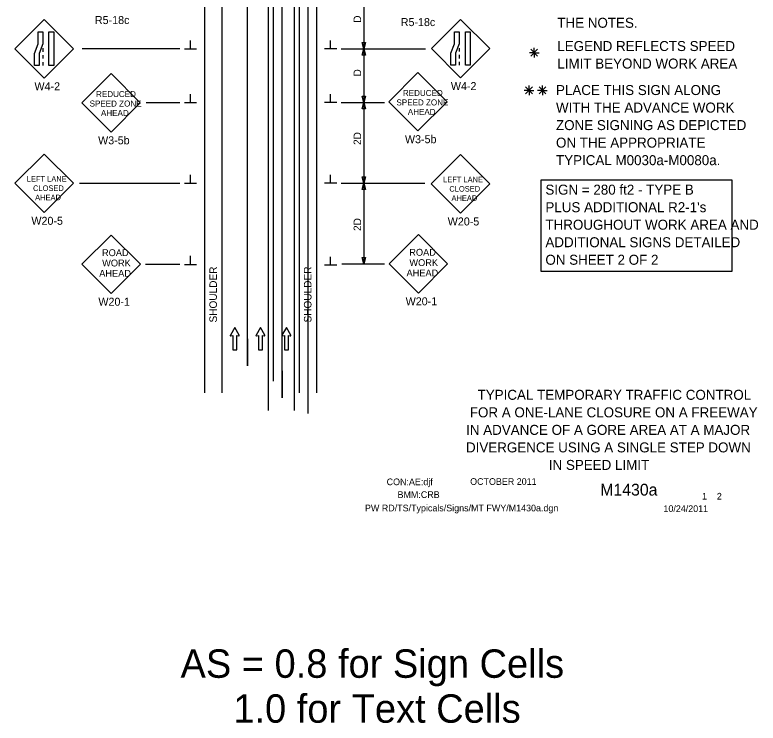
# Model space of a CAD drawing. Extents: x 16729 to 18500, y 5737 to 6974.
# Drawn here: x 16745 to 17436, y 5737 to 6395 of the extents above; entities that cross this region are included whole.
import ezdxf

# ---------------------------------------------------------------- set-up
doc = ezdxf.new("R2010")
doc.units = 0
for name, color, linetype in [('ALI_LEGAL_EX', 7, 'Continuous'), ('BORDER', 7, 'Continuous'), ('BORDER_SIGNAL_WO', 7, 'Continuous'), ('MT_SCRATCH_LEVEL_E', 7, 'Continuous'), ('PAVT_EDGE_EX', 7, 'Continuous'), ('TRAFFIC_SIGNS_PR', 7, 'Continuous'), ('TYPICAL_TEXT_DIMEN_EX', 7, 'Continuous'), ('TYPICAL_TEXT_DIMEN_PR', 7, 'Continuous')]:
    doc.layers.add(name, color=color, linetype=linetype)

msp = doc.modelspace()

# ---------------------------------------------------------------- linework, layer by layer
at = {"layer": 'ALI_LEGAL_EX'}
for p, q in [((16980.68, 6974.12), (16980.68, 6155.98)), ((17004.68, 6974.12), (17004.68, 6155.98)), ((16980.68, 6891.53), (16980.68, 6027.61)), ((17004.68, 6891.53), (17004.68, 6027.61)), ((16961.51, 6069.17), (16961.51, 6569.52)), ((16985.51, 6054.68), (16985.51, 6555.03)), ((16993.65, 6039.29), (16993.65, 6539.64)), ((17017.65, 6024.8), (17017.65, 6525.15))]:
    msp.add_line(p, q, dxfattribs=at)
for points in [[(16961.51, 6369.17), (16961.51, 6394.17)], [(16985.51, 6369.17), (16985.51, 6394.17)], [(16961.51, 6269.17), (16961.51, 6294.17)], [(16985.51, 6269.17), (16985.51, 6294.17)], [(16961.51, 6169.17), (16961.51, 6194.17)], [(16985.51, 6169.17), (16985.51, 6194.17)], [(16961.51, 6094.17), (16961.51, 6069.17)], [(16961.51, 6069.17), (16961.51, 6094.17)], [(16985.51, 6069.17), (16985.51, 6094.17)], [(16993.65, 6064.29), (16993.65, 6039.29)]]:
    msp.add_lwpolyline(points, dxfattribs=at)
at = {"layer": 'MT_SCRATCH_LEVEL_E'}
for p, q in [((16949.53, 6104.79), (16945.42, 6097.55)), ((16953.67, 6097.55), (16949.53, 6104.79)), ((16973.43, 6104.79), (16969.32, 6097.55)), ((16977.58, 6097.55), (16973.43, 6104.79)), ((16997.48, 6104.79), (16993.37, 6097.55)), ((17001.63, 6097.55), (16997.48, 6104.79)), ((16945.9, 6096.87), (16947.67, 6097.18)), ((16947.67, 6097.18), (16947.67, 6083.93)), ((16951.42, 6083.93), (16951.42, 6097.18)), ((16951.42, 6097.18), (16953.19, 6096.87)), ((16969.8, 6096.87), (16971.58, 6097.18)), ((16971.58, 6097.18), (16971.58, 6083.93)), ((16975.32, 6083.93), (16975.32, 6097.18)), ((16975.32, 6097.18), (16977.1, 6096.87)), ((16993.85, 6096.87), (16995.63, 6097.18)), ((16995.63, 6097.18), (16995.63, 6083.93)), ((16999.37, 6083.93), (16999.37, 6097.18)), ((16999.37, 6097.18), (17001.15, 6096.87)), ((16947.67, 6083.93), (16951.42, 6083.93)), ((16971.58, 6083.93), (16975.32, 6083.93)), ((16995.63, 6083.93), (16999.37, 6083.93))]:
    msp.add_line(p, q, dxfattribs=at)
for centre, start, end in [((16945.82, 6097.33), 150.42484, 279.96381), ((16953.26, 6097.33), 260.03619, 29.77312), ((16969.73, 6097.33), 150.42484, 279.96381), ((16977.17, 6097.33), 260.03619, 29.77312), ((16993.78, 6097.33), 150.42484, 279.96381), ((17001.22, 6097.33), 260.03619, 29.77312)]:
    msp.add_arc(centre, 0.463, start, end, dxfattribs=at)
at = {"layer": 'PAVT_EDGE_EX'}
for p, q in [((16921.51, 6569.52), (16921.51, 6043.9)), ((16937.51, 6569.52), (16937.51, 6043.9)), ((17009.51, 6569.52), (17009.51, 6043.9)), ((17025.51, 6569.52), (17025.51, 6043.9))]:
    msp.add_line(p, q, dxfattribs=at)
at = {"layer": 'TRAFFIC_SIGNS_PR'}
for p, q in [((16772.43, 6390.97), (16745.28, 6363.82)), ((16799.58, 6363.82), (16772.43, 6390.97)), ((17159.43, 6391.17), (17132.27, 6364.02)), ((17186.58, 6364.02), (17159.43, 6391.17)), ((16745.28, 6363.82), (16772.43, 6336.67)), ((16771.18, 6364.31), (16771.18, 6361.11)), ((16772.43, 6336.67), (16799.58, 6363.82)), ((17132.27, 6364.02), (17159.43, 6336.86)), ((17158.18, 6364.51), (17158.18, 6361.31)), ((17159.43, 6336.86), (17186.58, 6364.02)), ((16771.18, 6357.91), (16771.18, 6354.71)), ((17158.18, 6358.11), (17158.18, 6354.91)), ((16771.18, 6351.51), (16771.18, 6348.31)), ((17158.18, 6351.71), (17158.18, 6348.51)), ((17119.74, 6341.8), (17092.59, 6314.65)), ((17146.9, 6314.65), (17119.74, 6341.8)), ((16834.58, 6340.78), (16807.43, 6313.62)), ((16861.73, 6313.62), (16834.58, 6340.78)), ((16807.43, 6313.62), (16834.58, 6286.47)), ((16834.58, 6286.47), (16861.73, 6313.62)), ((17092.59, 6314.65), (17119.74, 6287.5)), ((17119.74, 6287.5), (17146.9, 6314.65)), ((16772.36, 6266), (16745.17, 6238.81)), ((16799.54, 6238.81), (16772.36, 6266)), ((17159.28, 6265.4), (17132.1, 6238.21)), ((17186.47, 6238.21), (17159.28, 6265.4)), ((16745.17, 6238.81), (16772.36, 6211.63)), ((16772.36, 6211.63), (16799.54, 6238.81)), ((17132.1, 6238.21), (17159.28, 6211.02)), ((17159.28, 6211.02), (17186.47, 6238.21)), ((16834.63, 6190.66), (16807.47, 6163.51)), ((16861.78, 6163.51), (16834.63, 6190.66)), ((17120.19, 6191.03), (17093.04, 6163.88)), ((17147.34, 6163.88), (17120.19, 6191.03)), ((16807.47, 6163.51), (16834.63, 6136.36)), ((16834.63, 6136.36), (16861.78, 6163.51)), ((17093.04, 6163.88), (17120.19, 6136.73)), ((17120.19, 6136.73), (17147.34, 6163.88))]:
    msp.add_line(p, q, dxfattribs=at)
for points in [[(16771.18, 6379.56), (16771.18, 6368.38), (16767.84, 6359.49), (16767.84, 6348.31), (16763.34, 6348.31), (16763.34, 6359.49), (16766.69, 6368.38), (16766.69, 6379.56)], [(16781.32, 6379.56), (16781.32, 6348.31), (16776.82, 6348.31), (16776.82, 6379.56)], [(17158.18, 6379.75), (17158.18, 6368.57), (17154.83, 6359.69), (17154.83, 6348.51), (17150.34, 6348.51), (17150.34, 6359.69), (17153.68, 6368.57), (17153.68, 6379.75)], [(17168.31, 6379.75), (17168.31, 6348.51), (17163.82, 6348.51), (17163.82, 6379.75)]]:
    msp.add_lwpolyline(points, close=True, dxfattribs=at)
at = {"layer": 'TYPICAL_TEXT_DIMEN_EX'}
msp.add_lwpolyline([(17234.19, 6242.04), (17411.46, 6242.04), (17411.46, 6156.72), (17234.19, 6156.72)], close=True, dxfattribs=at)
at = {"layer": 'TYPICAL_TEXT_DIMEN_PR'}
for p, q in [((17069.51, 6413.85), (17069.51, 6363.85)), ((16908.39, 6363.85), (16908.39, 6371.64)), ((17038.64, 6363.85), (17038.64, 6371.64)), ((17069.51, 6363.85), (17067.94, 6369.72)), ((17067.94, 6369.72), (17069.51, 6369.72)), ((17069.51, 6369.72), (17071.08, 6369.72)), ((17071.08, 6369.72), (17069.51, 6363.85)), ((16898.51, 6363.85), (16807.65, 6363.85)), ((16902.76, 6363.85), (16914.01, 6363.85)), ((17044.26, 6363.85), (17033.01, 6363.85)), ((17048.51, 6363.85), (17126.72, 6363.85)), ((17067.94, 6357.99), (17069.51, 6363.85)), ((17069.51, 6363.85), (17069.51, 6313.85)), ((17069.51, 6363.85), (17071.08, 6357.99)), ((17224.66, 6363.4), (17231.04, 6357.03)), ((17231.04, 6363.4), (17224.66, 6357.03)), ((17227.85, 6360.22), (17227.85, 6364.67)), ((17069.51, 6357.99), (17067.94, 6357.99)), ((17071.08, 6357.99), (17069.51, 6357.99)), ((17227.85, 6360.22), (17223.32, 6360.22)), ((17227.85, 6360.22), (17231.04, 6360.22)), ((17227.85, 6360.22), (17232.33, 6360.22)), ((17227.85, 6360.22), (17227.85, 6355.72)), ((17219.8, 6328.35), (17226.18, 6321.97)), ((17226.18, 6328.35), (17219.8, 6321.97)), ((17222.99, 6325.16), (17222.99, 6329.61)), ((17238.73, 6328.35), (17232.35, 6321.97)), ((17232.36, 6328.35), (17238.73, 6321.97)), ((17235.54, 6325.16), (17235.54, 6329.61)), ((16908.39, 6313.85), (16908.39, 6321.64)), ((17038.64, 6313.85), (17038.64, 6321.64)), ((17222.99, 6325.16), (17218.46, 6325.16)), ((17222.99, 6325.16), (17226.18, 6325.16)), ((17222.99, 6325.16), (17227.47, 6325.16)), ((17222.99, 6325.16), (17222.99, 6320.66)), ((17235.54, 6325.16), (17231.01, 6325.16)), ((17235.54, 6325.16), (17238.73, 6325.16)), ((17235.54, 6325.16), (17240.02, 6325.16)), ((17235.54, 6325.16), (17235.54, 6320.66)), ((16867.35, 6313.85), (16898.51, 6313.85)), ((16902.76, 6313.85), (16914.01, 6313.85)), ((17044.26, 6313.85), (17033.01, 6313.85)), ((17048.51, 6313.85), (17088.78, 6313.85)), ((17069.51, 6313.85), (17067.94, 6319.72)), ((17067.94, 6319.72), (17069.51, 6319.72)), ((17067.94, 6307.99), (17069.51, 6313.85)), ((17069.51, 6319.72), (17071.08, 6319.72)), ((17071.08, 6319.72), (17069.51, 6313.85)), ((17069.51, 6313.85), (17069.51, 6238.85)), ((17069.51, 6313.85), (17071.08, 6307.99)), ((17069.51, 6307.99), (17067.94, 6307.99)), ((17071.08, 6307.99), (17069.51, 6307.99)), ((16908.39, 6238.85), (16908.39, 6246.64)), ((17038.64, 6238.85), (17038.64, 6246.64)), ((17069.51, 6238.85), (17067.94, 6244.72)), ((17067.94, 6244.72), (17069.51, 6244.72)), ((17069.51, 6244.72), (17071.08, 6244.72)), ((17071.08, 6244.72), (17069.51, 6238.85)), ((16805.28, 6238.85), (16898.51, 6238.85)), ((16902.76, 6238.85), (16914.01, 6238.85)), ((17044.26, 6238.85), (17033.01, 6238.85)), ((17048.51, 6238.85), (17126.06, 6238.85)), ((17067.94, 6232.99), (17069.51, 6238.85)), ((17069.51, 6238.85), (17069.51, 6163.85)), ((17069.51, 6238.85), (17071.08, 6232.99)), ((17069.51, 6232.99), (17067.94, 6232.99)), ((17071.08, 6232.99), (17069.51, 6232.99)), ((16908.39, 6163.41), (16908.39, 6171.19)), ((17038.64, 6162.64), (17038.64, 6170.42)), ((17069.51, 6163.85), (17067.94, 6169.72)), ((17067.94, 6169.72), (17069.51, 6169.72)), ((17069.51, 6169.72), (17071.08, 6169.72)), ((17071.08, 6169.72), (17069.51, 6163.85)), ((16898.51, 6163.41), (16866.57, 6163.41)), ((16902.76, 6163.41), (16914.01, 6163.41)), ((17044.26, 6162.64), (17033.01, 6162.64)), ((17049.01, 6163.85), (17088.78, 6163.85))]:
    msp.add_line(p, q, dxfattribs=at)

# ---------------------------------------------------------------- texts
at = {"layer": 'BORDER'}
for s, p in [('TYPICAL TEMPORARY TRAFFIC CONTROL', (17175.21, 6037.44)), ('FOR A ONE-LANE CLOSURE ON A FREEWAY', (17167.99, 6021.14)), ('IN ADVANCE OF A GORE AREA AT A MAJOR', (17164.54, 6004.84)), ('DIVERGENCE USING A SINGLE STEP DOWN ', (17164.42, 5988.54)), ('IN SPEED LIMIT', (17241.42, 5972.24))]:
    msp.add_text(s, height=9.3, dxfattribs=at).set_placement(p)
at = {"layer": 'BORDER_SIGNAL_WO'}
for s, height, p in [('CON:AE:djf  ', 6.2, (17090.69, 5958.06)), ('    OCTOBER 2011    ', 6.2, (17159.08, 5958.34)), ('    M1430a   ', 11, (17272.86, 5948.38)), ('BMM:CRB   ', 6.2, (17100.81, 5946.17)), (' 1    2 ', 6.2, (17381.45, 5944.7)), ('PW RD/TS/Typicals/Signs/MT FWY/M1430a.dgn      ', 6.2, (17070.55, 5933.71)), ('10/24/2011    ', 6.2, (17347.93, 5933.13)), ('AS = 0.8 for Sign Cells', 26.4241, (16899.12, 5778.94)), ('     1.0 for Text Cells', 26.4241, (16899.12, 5737.16))]:
    msp.add_text(s, height=height, dxfattribs=at).set_placement(p)
at = {"layer": 'TRAFFIC_SIGNS_PR'}
for s, height, p in [('R5-18c', 7.44, (16819.56, 6386.84)), ('R5-18c', 7.44, (17103.81, 6384.96)), ('W4-2', 7.44, (16763.39, 6325.23)), ('W4-2', 7.44, (17150.38, 6325.43)), ('REDUCED', 5.6, (16820.64, 6318.93)), ('REDUCED', 5.6, (17105.8, 6319.96)), ('SPEED ZONE', 5.6, (16814.63, 6310.13)), ('SPEED ZONE', 5.6, (17099.79, 6311.16)), ('AHEAD', 5.6, (16825.19, 6301.33)), ('AHEAD', 5.6, (17110.35, 6302.36)), ('W3-5b', 7.44, (16822.53, 6275.03)), ('W3-5b', 7.44, (17107.7, 6276.06)), ('LEFT LANE', 5.206, (16756.22, 6240.21)), ('LEFT LANE', 5.206, (17143.14, 6239.61)), ('CLOSED', 5.206, (16762.06, 6231.6)), ('CLOSED', 5.206, (17148.98, 6231)), ('AHEAD', 5.206, (16764.01, 6222.99)), ('AHEAD', 5.206, (17150.93, 6222.39)), ('W20-5', 7.449, (16760.52, 6200.17)), ('W20-5', 7.449, (17147.44, 6199.57)), ('ROAD', 6.4, (16826.17, 6171.05)), ('ROAD', 6.4, (17111.73, 6171.41)), ('WORK', 6.4, (16826.28, 6161.45)), ('WORK', 6.4, (17111.84, 6161.81)), ('AHEAD', 6.4, (16823.59, 6151.85)), ('AHEAD', 6.4, (17109.15, 6152.21)), ('W20-1', 7.44, (16822.8, 6124.92)), ('W20-1', 7.44, (17108.36, 6125.29))]:
    msp.add_text(s, height=height, dxfattribs=at).set_placement(p)
at = {"layer": 'TYPICAL_TEXT_DIMEN_EX'}
for s, p in [('THE NOTES.', (17249.3, 6383.38)), ('LEGEND REFLECTS SPEED', (17249.3, 6361.75)), ('LIMIT BEYOND WORK AREA', (17249.3, 6345.45)), ('PLACE THIS SIGN ALONG', (17248.08, 6320.83)), ('WITH THE ADVANCE WORK', (17248.08, 6304.53)), ('ZONE SIGNING AS DEPICTED', (17248.08, 6288.23)), ('ON THE APPROPRIATE', (17248.08, 6271.93)), ('TYPICAL M0030a-M0080a.', (17248.08, 6255.63)), ('SIGN = 280 ft2 - TYPE B', (17238.24, 6228.21)), ("PLUS ADDITIONAL R2-1's", (17238.24, 6211.91)), ('THROUGHOUT WORK AREA AND', (17238.24, 6195.61)), ('ADDITIONAL SIGNS DETAILED', (17238.24, 6179.31)), ('ON SHEET 2 OF 2', (17238.24, 6163.01))]:
    msp.add_text(s, height=9.3, dxfattribs=at).set_placement(p)
at = {"layer": 'TYPICAL_TEXT_DIMEN_PR'}
for s, p in [('D', (17066.95, 6388.07)), ('D', (17066.95, 6338.07)), ('2D', (17066.95, 6274.41)), ('2D', (17066.95, 6194.43)), ('SHOULDER', (16932.95, 6109.34)), ('SHOULDER', (17020.81, 6109.34))]:
    msp.add_text(s, height=7, rotation=90, dxfattribs=at).set_placement(p)

doc.saveas('drawing.dxf')
